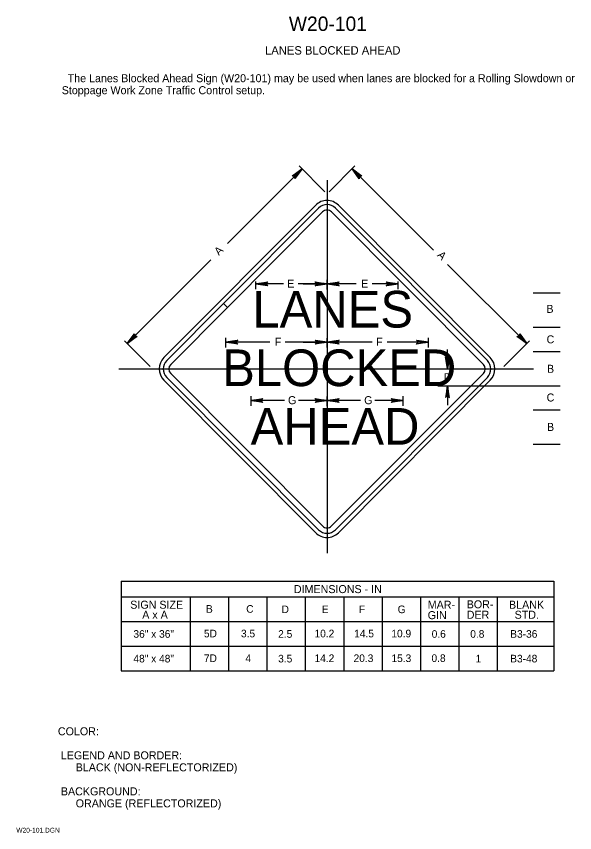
# Model space of a CAD drawing. Extents: x 0.013 to 0.187, y 0.004 to 0.259.
import ezdxf

# ---------------------------------------------------------------- set-up
doc = ezdxf.new("R2010")
doc.units = 0
for name, color, linetype in [('1', 7, 'Continuous'), ('2', 7, 'Continuous'), ('3', 7, 'Continuous')]:
    doc.layers.add(name, color=color, linetype=linetype)

# ---------------------------------------------------------------- blocks, each defined once
blk = doc.blocks.new('RARROW')
at = {"layer": '3'}
for p, q in [((-2.156, 0.28500000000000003), (-2.2665, 0.384625)), ((-2.2665, 0.384625), (0, 0)), ((0, 0), (-2.2665, -0.379125)), ((-2.156, 0.28500000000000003), (-2.075625, 0.12075)), ((0, 0), (-2.156, 0.28500000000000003)), ((-2.14975, -0.2705), (0, 0)), ((-2.075625, 0.12075), (0, 0)), ((0, 0), (-2.074, -0.108)), ((-2.2665, -0.379125), (-2.14975, -0.2705)), ((-2.074, -0.108), (-2.14975, -0.2705))]:
    blk.add_line(p, q, dxfattribs=at)

msp = doc.modelspace()

# ---------------------------------------------------------------- linework, layer by layer
at = {"layer": '1'}
msp.add_line((0.18044683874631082, 0.08285917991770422), (0.18044683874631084, 0.0548262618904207), dxfattribs=at)
at = {"layer": '3'}
for p, q in [((0.07849348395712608, 0.1883021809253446), (0.1017987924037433, 0.21160748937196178)), ((0.10895824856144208, 0.20444803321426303), (0.10091490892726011, 0.212491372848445)), ((0.11027264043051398, 0.20444803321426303), (0.11831598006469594, 0.212491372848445)), ((0.14289279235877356, 0.186146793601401), (0.11743209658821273, 0.21160748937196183)), ((0.10961544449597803, 0.20808978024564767), (0.10961544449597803, 0.09165601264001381)), ((0.10607446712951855, 0.2002476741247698), (0.05861869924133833, 0.15264543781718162)), ((0.07726978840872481, 0.16953132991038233), (0.10698584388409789, 0.1993391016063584)), ((0.11224504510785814, 0.1993391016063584), (0.15970081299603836, 0.15173686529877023)), ((0.16061218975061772, 0.15264543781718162), (0.11315642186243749, 0.2002476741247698)), ((0.10820103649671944, 0.19812764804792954), (0.07848124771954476, 0.16831613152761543)), ((0.15848562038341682, 0.15052541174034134), (0.11102985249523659, 0.19812764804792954)), ((0.07334154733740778, 0.18315024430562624), (0.047200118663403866, 0.1570088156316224)), ((0.14727193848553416, 0.18176764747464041), (0.17203077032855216, 0.1570088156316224)), ((0.08739444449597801, 0.17400007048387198), (0.08739444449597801, 0.17636282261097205)), ((0.10961544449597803, 0.173905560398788), (0.10961544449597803, 0.17690089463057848)), ((0.131836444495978, 0.17400007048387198), (0.131836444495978, 0.17636282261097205)), ((0.09597969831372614, 0.17565089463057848), (0.08739444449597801, 0.17565089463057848)), ((0.10961544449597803, 0.17565089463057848), (0.10061069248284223, 0.17565089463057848)), ((0.10211544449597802, 0.17565089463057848), (0.10711544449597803, 0.17565089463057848)), ((0.11866211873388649, 0.17565089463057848), (0.10961544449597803, 0.17565089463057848)), ((0.131836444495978, 0.17565089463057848), (0.12367115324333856, 0.17565089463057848)), ((0.18240917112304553, 0.1727520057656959), (0.1739804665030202, 0.1727520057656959)), ((0.05953007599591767, 0.15173686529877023), (0.07726978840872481, 0.16953132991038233)), ((0.07848124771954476, 0.16831613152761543), (0.06074526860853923, 0.15052541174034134)), ((0.07726978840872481, 0.16953132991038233), (0.07848124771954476, 0.16831613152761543)), ((0.07848124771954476, 0.16831613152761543), (0.07726978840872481, 0.16953132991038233)), ((0.18240917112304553, 0.16202757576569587), (0.1739804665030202, 0.16202757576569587)), ((0.07795694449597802, 0.1558541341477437), (0.07795694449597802, 0.15887845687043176)), ((0.10961544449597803, 0.15575962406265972), (0.10961544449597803, 0.15875495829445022)), ((0.14127394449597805, 0.1558541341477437), (0.14127394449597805, 0.15887845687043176)), ((0.05435957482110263, 0.14984935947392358), (0.04631623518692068, 0.15789269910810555)), ((0.09172674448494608, 0.15750495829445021), (0.07795694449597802, 0.15750495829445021)), ((0.10961544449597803, 0.15750495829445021), (0.09654675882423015, 0.15750495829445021)), ((0.10211544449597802, 0.15750495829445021), (0.10711544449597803, 0.15750495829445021)), ((0.12367115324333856, 0.15750495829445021), (0.10961544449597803, 0.15750495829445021)), ((0.14127394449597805, 0.15750495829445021), (0.12839665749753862, 0.15750495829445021)), ((0.16487131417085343, 0.14984935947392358), (0.1729146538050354, 0.15789269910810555)), ((0.14724156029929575, 0.14911535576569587), (0.14724156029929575, 0.15520028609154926)), ((0.18240917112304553, 0.15447757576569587), (0.1739804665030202, 0.15447757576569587)), ((0.04453805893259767, 0.14911535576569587), (0.17409316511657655, 0.14911535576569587)), ((0.10607446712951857, 0.09798303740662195), (0.058618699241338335, 0.14558527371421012)), ((0.10698584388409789, 0.09889160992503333), (0.05953007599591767, 0.14649384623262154)), ((0.06074526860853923, 0.14770529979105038), (0.10820103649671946, 0.10010306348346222)), ((0.1110298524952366, 0.10010306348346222), (0.15848562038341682, 0.14770529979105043)), ((0.15970081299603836, 0.14649384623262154), (0.11224504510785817, 0.09889160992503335)), ((0.16061218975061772, 0.14558527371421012), (0.11315642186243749, 0.09798303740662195)), ((0.18240917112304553, 0.14375313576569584), (0.14422709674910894, 0.14375313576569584)), ((0.14724156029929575, 0.14391566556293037), (0.14724156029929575, 0.137830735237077)), ((0.08585014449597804, 0.13761368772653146), (0.08585014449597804, 0.1406380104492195)), ((0.10961544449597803, 0.13751917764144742), (0.10961544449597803, 0.14051451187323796)), ((0.13342783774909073, 0.13761368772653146), (0.13342783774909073, 0.1406380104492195)), ((0.0962673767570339, 0.13926451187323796), (0.08580305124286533, 0.13926451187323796)), ((0.10961544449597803, 0.13926451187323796), (0.10070935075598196, 0.13926451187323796)), ((0.1200797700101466, 0.13926451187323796), (0.10961544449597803, 0.13926451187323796)), ((0.13342783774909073, 0.13926451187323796), (0.12452174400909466, 0.13926451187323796)), ((0.18240917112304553, 0.13620313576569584), (0.1739804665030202, 0.13620313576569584)), ((0.18240917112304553, 0.12547870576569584), (0.1739804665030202, 0.12547870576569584)), ((0.045321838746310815, 0.08285917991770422), (0.18044683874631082, 0.08285917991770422)), ((0.045321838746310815, 0.08285917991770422), (0.045321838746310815, 0.0548262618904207)), ((0.18044683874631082, 0.07785917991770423), (0.045321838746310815, 0.07785917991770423)), ((0.06682183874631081, 0.07785917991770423), (0.06682183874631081, 0.0548262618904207)), ((0.07882183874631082, 0.07785917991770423), (0.07882183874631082, 0.0548262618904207)), ((0.09082183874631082, 0.07785917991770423), (0.09082183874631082, 0.0548262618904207)), ((0.10282183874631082, 0.07785917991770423), (0.10282183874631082, 0.0548262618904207)), ((0.11482183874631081, 0.07785917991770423), (0.11482183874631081, 0.0548262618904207)), ((0.1268218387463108, 0.07785917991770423), (0.1268218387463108, 0.0548262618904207)), ((0.13882183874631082, 0.07785917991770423), (0.13882183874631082, 0.054826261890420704)), ((0.13882183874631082, 0.07785917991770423), (0.13882183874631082, 0.06253022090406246)), ((0.15082183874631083, 0.07785917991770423), (0.15082183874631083, 0.054826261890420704)), ((0.16282183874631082, 0.07785917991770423), (0.16282183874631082, 0.054826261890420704)), ((0.045321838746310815, 0.07023417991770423), (0.18044683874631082, 0.07023417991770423)), ((0.045321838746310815, 0.06253022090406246), (0.18044683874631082, 0.06253022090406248)), ((0.045321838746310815, 0.0548262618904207), (0.18044683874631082, 0.054826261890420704))]:
    msp.add_line(p, q, dxfattribs=at)
for centre, radius, start, end in [((0.10961544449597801, 0.19671759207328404), 0.005, 44.91171689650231, 135.08828310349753), ((0.10961544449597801, 0.19671759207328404), 0.0037130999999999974, 44.91171689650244, 135.08828310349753), ((0.10961544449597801, 0.19671759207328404), 0.001997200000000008, 44.91171689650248, 135.08828310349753), ((0.0621596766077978, 0.14911535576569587), 0.005, 135.08828310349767, 224.91171689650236), ((0.0621596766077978, 0.14911535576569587), 0.0037131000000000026, 135.08828310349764, 224.9117168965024), ((0.0621596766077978, 0.14911535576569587), 0.001997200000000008, 135.08828310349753, 224.91171689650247), ((0.15707121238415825, 0.14911535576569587), 0.001997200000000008, 315.08828310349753, 44.91171689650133), ((0.15707121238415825, 0.14911535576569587), 0.0037130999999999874, 315.08828310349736, 44.91171689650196), ((0.15707121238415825, 0.14911535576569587), 0.005, 315.08828310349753, 44.911716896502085), ((0.10961544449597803, 0.1015131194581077), 0.001997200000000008, 224.91171689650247, 315.08828310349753), ((0.10961544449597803, 0.1015131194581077), 0.005, 224.91171689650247, 315.0882831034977), ((0.10961544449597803, 0.1015131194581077), 0.003713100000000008, 224.91171689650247, 315.0882831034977)]:
    msp.add_arc(centre, radius, start, end, dxfattribs=at)

# ---------------------------------------------------------------- block references
for p, xscale, yscale, rotation in [((0.1017987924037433, 0.21160748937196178), 0.0016545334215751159, 0.0016366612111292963, 44.99999999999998), ((0.11743209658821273, 0.21160748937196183), 0.001654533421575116, 0.001636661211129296, 135), ((0.08739444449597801, 0.17565089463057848), 0.0016545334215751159, 0.0016366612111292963, 180), ((0.10961544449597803, 0.17565089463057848), 0.0016545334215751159, 0.0016366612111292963, 180), ((0.047200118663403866, 0.1570088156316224), 0.0016545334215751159, 0.001636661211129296, -135), ((0.07795694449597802, 0.15750495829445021), 0.0016545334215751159, 0.0016366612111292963, 180), ((0.10961544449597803, 0.15750495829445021), 0.0016545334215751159, 0.0016366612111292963, 180), ((0.17203077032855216, 0.1570088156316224), 0.0016545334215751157, 0.001636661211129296, -45), ((0.14724156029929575, 0.14911535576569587), 0.0016545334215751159, 0.0016366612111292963, -90.00000000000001), ((0.14724156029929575, 0.1439156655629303), 0.0016545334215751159, -0.0016366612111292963, 90.00000000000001), ((0.08580305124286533, 0.13926451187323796), 0.0016545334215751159, 0.0016366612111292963, 180), ((0.10961544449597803, 0.13926451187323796), 0.0016545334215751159, 0.0016366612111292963, 180)]:
    msp.add_blockref('RARROW', p, dxfattribs=dict(at, xscale=xscale, yscale=yscale, rotation=rotation))
at = {"layer": '3', "xscale": 0.0016545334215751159, "yscale": 0.0016366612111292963}
for p in [(0.10961544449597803, 0.17565089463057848), (0.131836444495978, 0.17565089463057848), (0.10961544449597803, 0.15750495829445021), (0.14127394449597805, 0.15750495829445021), (0.10961544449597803, 0.13926451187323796), (0.13342783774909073, 0.13926451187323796)]:
    msp.add_blockref('RARROW', p, dxfattribs=at)

# ---------------------------------------------------------------- texts
at = {"layer": '1'}
for s, height, p in [('W20-101', 0.0045000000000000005, (0.09766568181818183, 0.254625)), ('LANES BLOCKED AHEAD', 0.002625, (0.09022482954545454, 0.24725)), ('COLOR:', 0.0024997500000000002, (0.025500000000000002, 0.034749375)), (' LEGEND AND BORDER:', 0.0024997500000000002, (0.025500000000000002, 0.027249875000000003)), ('      BLACK (NON-REFLECTORIZED)', 0.0024997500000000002, (0.025500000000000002, 0.023500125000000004)), (' BACKGROUND:', 0.0024997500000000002, (0.025500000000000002, 0.016000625)), ('      ORANGE (REFLECTORIZED)', 0.0024997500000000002, (0.025500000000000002, 0.012250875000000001)), ('W20-101.DGN', 0.0015, (0.0125, 0.004375))]:
    msp.add_text(s, height=height, dxfattribs=at).set_placement(p)
at = {"layer": '2'}
for s, p in [('  The Lanes Blocked Ahead Sign (W20-101) may be used when lanes are blocked for a Rolling Slowdown or', (0.026696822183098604, 0.23862487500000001)), ('Stoppage Work Zone Traffic Control setup.', (0.026696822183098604, 0.234875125))]:
    msp.add_text(s, height=0.0024997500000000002, dxfattribs=at).set_placement(p)
at = {"layer": '3'}
for s, height, rotation, p in [('A', 0.0025, 45, (0.07582509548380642, 0.18438121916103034)), ('A', 0.0025, 315, (0.1438568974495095, 0.18444530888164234)), ('BLOCKED', 0.01144664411, 360, (0.07684279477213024, 0.14375150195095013)), ('14.5', 0.0023752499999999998, 360, (0.11808412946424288, 0.06532815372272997)), ('20.3', 0.0023752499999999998, 360, (0.11789986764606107, 0.0576241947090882))]:
    msp.add_text(s, height=height, rotation=rotation, dxfattribs=at).set_placement(p)
for s, height, p in [('E', 0.0024997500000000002, (0.097158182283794, 0.1744984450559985)), ('E', 0.0024997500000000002, (0.1202505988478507, 0.1744984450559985)), ('LANES', 0.01144664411, (0.08629067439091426, 0.16204087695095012)), ('B', 0.0024997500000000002, (0.17815312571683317, 0.16662491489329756)), ('F', 0.0024997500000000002, (0.0932851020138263, 0.15635250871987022)), ('F', 0.0024997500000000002, (0.12494414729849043, 0.15635250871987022)), ('C', 0.0024997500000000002, (0.17822425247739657, 0.15710003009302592)), ('B', 0.0024997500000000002, (0.17834214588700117, 0.14791191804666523)), ('D', 0.0024997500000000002, (0.14607827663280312, 0.1452656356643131)), ('G', 0.0024997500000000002, (0.09740643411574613, 0.1381120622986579)), ('G', 0.0024997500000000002, (0.12121882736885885, 0.1381120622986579)), ('C', 0.0024997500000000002, (0.17822425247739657, 0.13895409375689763)), ('AHEAD', 0.01144664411, (0.08573858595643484, 0.1254621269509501)), ('B', 0.0024997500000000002, (0.17834214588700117, 0.12976598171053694)), ('DIMENSIONS - IN', 0.0024997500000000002, (0.09924744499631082, 0.07914077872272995)), ('SIGN SIZE', 0.0024997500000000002, (0.04810963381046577, 0.07426278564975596)), ('MAR-', 0.0024997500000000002, (0.14107285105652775, 0.07425679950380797)), ('BOR-', 0.0024997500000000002, (0.15325999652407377, 0.07438778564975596)), ('BLANK', 0.0024997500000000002, (0.1664763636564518, 0.07425979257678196)), ('B', 0.0023752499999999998, (0.07178480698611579, 0.07301278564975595)), ('C', 0.0023752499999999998, (0.08434695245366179, 0.07301278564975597)), ('D', 0.0023752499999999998, (0.09541433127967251, 0.07288479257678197)), ('E', 0.0023752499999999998, (0.10795669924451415, 0.07288479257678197)), ('F', 0.0023752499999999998, (0.11956090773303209, 0.07288479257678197)), ('G', 0.0023752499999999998, (0.13168459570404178, 0.07288479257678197)), ('A x A', 0.0024997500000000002, (0.051859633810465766, 0.07113778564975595)), ('GIN', 0.0024997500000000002, (0.14107285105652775, 0.07100679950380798)), ('DER', 0.0024997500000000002, (0.15325999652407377, 0.07113778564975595)), ('STD.', 0.0024997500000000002, (0.16822636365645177, 0.07113479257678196)), ('36" x 36"', 0.0023752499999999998, (0.049108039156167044, 0.06520016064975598)), ('5D', 0.0023752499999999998, (0.07113735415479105, 0.06532815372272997)), ('3.5', 0.0023752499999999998, (0.0827183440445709, 0.06533114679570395)), ('2.5', 0.0023752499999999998, (0.09433791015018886, 0.06520016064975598)), ('10.2', 0.0023752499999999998, (0.10569807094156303, 0.06532815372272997)), ('10.9', 0.0023752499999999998, (0.12971290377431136, 0.06532815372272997)), ('0.6', 0.0023752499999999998, (0.14231037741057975, 0.06520016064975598)), ('0.8', 0.0023752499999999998, (0.15436555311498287, 0.06520315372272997)), ('B3-36', 0.0023752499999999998, (0.16685877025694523, 0.06520614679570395)), ('48" x 48"', 0.0023752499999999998, (0.049108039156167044, 0.0574962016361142)), ('7D', 0.0023752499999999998, (0.07113735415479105, 0.0576241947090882)), ('4', 0.0023752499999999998, (0.08410750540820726, 0.057627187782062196)), ('3.5', 0.0023752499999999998, (0.09433791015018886, 0.05749620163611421)), ('14.2', 0.0023752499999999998, (0.10569807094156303, 0.0576241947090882)), ('15.3', 0.0023752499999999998, (0.12974385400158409, 0.0576241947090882)), ('0.8', 0.0023752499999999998, (0.14224933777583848, 0.05765256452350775)), ('1', 0.0023752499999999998, (0.15602894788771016, 0.0574991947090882)), ('B3-48', 0.0023752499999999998, (0.1668458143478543, 0.057502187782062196))]:
    msp.add_text(s, height=height, dxfattribs=at).set_placement(p)

doc.saveas('drawing.dxf')
